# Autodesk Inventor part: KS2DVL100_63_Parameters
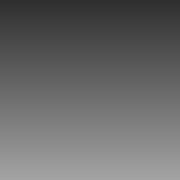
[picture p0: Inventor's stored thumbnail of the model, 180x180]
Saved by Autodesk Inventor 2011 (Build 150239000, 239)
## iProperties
Created: 2010-11
Document SubType Name: Modeling
Designer: TB
Density: 1 g/cm^3
Slaglengde: 100,000 mm
Vinkel_Minusport: 0.00 deg
Forlengelse_rør: 0.000 mm
Minusport2: 180.00 deg
Author: TB
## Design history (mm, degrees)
other parameters: "Slaglengde" = 100 [user parameter], "Forlengelse_rør" = 0 [user parameter], "Vinkel_Minusport" = 0 deg [user parameter], "Minusport2" = 180 deg [user parameter]
